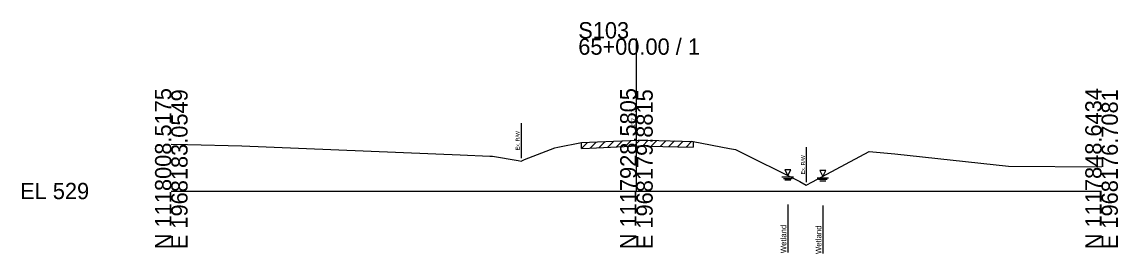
# Model space of a CAD drawing. Extents: x -26 to 163, y -10 to 24018.
# Drawn here: x -25.7 to 162.8, y 12989.2 to 13029.1 of the extents above; entities that cross this region are included whole.
import ezdxf

# ---------------------------------------------------------------- set-up
doc = ezdxf.new("R2010")
doc.units = 0
for name, color, linetype in [('RD_GPK_XS_Cell', 7, 'Continuous'), ('RD_XS_ExGround', 7, 'Continuous'), ('RD_XS_ExPaveRet', 7, 'Continuous'), ('RD_XS_ExRW', 7, 'Continuous'), ('RD_XS_EXWetland', 7, 'Continuous'), ('RD_XS_TX_Elev_EX', 7, 'Continuous')]:
    doc.layers.add(name, color=color, linetype=linetype)

msp = doc.modelspace()

# ---------------------------------------------------------------- linework, layer by layer
at = {"layer": 'RD_GPK_XS_Cell'}
for p, q in [((80, 13000), (80, 13026.22)), ((0, 13000), (80, 13000)), ((80, 13000), (160, 13000))]:
    msp.add_line(p, q, dxfattribs=at)
at = {"layer": 'RD_XS_ExGround'}
msp.add_lwpolyline([(0, 13008.03), (2.77, 13007.97), (12.12, 13007.77), (49.68, 13006.23), (54.81, 13005.99), (55.25, 13005.97), (59.64, 13005.23), (60.15, 13005.15), (60.75, 13005.39), (65.97, 13007.4), (66.48, 13007.51), (70.56, 13008.31), (71.92, 13008.37), (80.28, 13008.74), (81.93, 13008.72), (89.75, 13008.53), (96, 13007.33), (97.04, 13007.15), (108.1, 13001.62), (109.22, 13001.02), (110.29, 13001.57), (120.04, 13006.78), (124.45, 13006.4), (144.02, 13004.28), (160, 13004.13)], dxfattribs=at)
at = {"layer": 'RD_XS_ExPaveRet'}
for p, q in [((70.56, 13007.31), (71.6, 13008.35)), ((70.56, 13007.31), (70.56, 13008.31)), ((70.56, 13007.31), (71.92, 13007.37)), ((71.92, 13007.37), (80.28, 13007.74)), ((72.06, 13007.37), (73.1, 13008.42)), ((73.56, 13007.44), (74.6, 13008.49)), ((75.06, 13007.51), (76.1, 13008.55)), ((76.56, 13007.57), (77.6, 13008.62)), ((78.06, 13007.64), (79.1, 13008.69)), ((79.56, 13007.71), (80.59, 13008.73)), ((80.28, 13007.74), (81.93, 13007.72)), ((81.06, 13007.73), (82.04, 13008.72)), ((81.93, 13007.72), (89.75, 13007.53)), ((82.56, 13007.7), (83.53, 13008.68)), ((84.06, 13007.67), (85.03, 13008.64)), ((85.56, 13007.63), (86.53, 13008.61)), ((87.06, 13007.6), (88.04, 13008.57)), ((88.56, 13007.56), (89.54, 13008.54)), ((89.75, 13008.53), (89.75, 13007.53))]:
    msp.add_line(p, q, dxfattribs=at)
at = {"layer": 'RD_XS_ExRW'}
for p, q in [((60.15, 13011.65), (60.15, 13005.65)), ((109.22, 13007.52), (109.22, 13001.52))]:
    msp.add_line(p, q, dxfattribs=at)
at = {"layer": 'RD_XS_EXWetland'}
for p, q in [((105.53, 13003.66), (106.03, 13002.66)), ((106.53, 13003.66), (105.53, 13003.66)), ((106.03, 13002.66), (106.53, 13003.66)), ((111.56, 13003.51), (112.06, 13002.51)), ((112.56, 13003.51), (111.56, 13003.51)), ((112.06, 13002.51), (112.56, 13003.51)), ((105.03, 13002.41), (107.03, 13002.41)), ((105.28, 13002.16), (106.78, 13002.16)), ((105.53, 13001.91), (106.53, 13001.91)), ((111.06, 13002.26), (113.06, 13002.26)), ((111.31, 13002.01), (112.81, 13002.01)), ((111.56, 13001.76), (112.56, 13001.76)), ((106.03, 12997.66), (106.03, 12989.41)), ((112.06, 12997.51), (112.06, 12989.26))]:
    msp.add_line(p, q, dxfattribs=at)

# ---------------------------------------------------------------- texts
at = {"layer": 'RD_GPK_XS_Cell'}
for s, p in [('S103', (70, 13026.22)), ('65+00.00 / 1', (70, 13023.42)), ('EL 529', (-26, 12998.6))]:
    msp.add_text(s, height=2.8, dxfattribs=at).set_placement(p)
for s, p in [('N 1118008.5175', (0, 12990)), ('E 1968183.0549', (2.8, 12990)), ('N 1117928.5805', (80, 12990)), ('E 1968179.8815', (82.8, 12990)), ('N 1117848.6434', (160, 12990)), ('E 1968176.7081', (162.8, 12990))]:
    msp.add_text(s, height=2.8, rotation=90, dxfattribs=at).set_placement(p)
at = {"layer": 'RD_XS_ExRW'}
for p in [(59.9, 13007), (108.97, 13002.86)]:
    msp.add_text('Ex. R/W ', height=0.65, rotation=90, dxfattribs=at).set_placement(p)
at = {"layer": 'RD_XS_EXWetland'}
for p in [(105.78, 12989.3), (111.81, 12989.16)]:
    msp.add_text('Wetland ', height=1, rotation=90, dxfattribs=at).set_placement(p)
at = {"layer": 'RD_XS_TX_Elev_EX'}
msp.add_text('537.73', height=0.8, rotation=90, dxfattribs=at).set_placement((79.9, 13010.73))

doc.saveas('drawing.dxf')
